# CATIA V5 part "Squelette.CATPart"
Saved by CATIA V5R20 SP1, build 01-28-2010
Part number: Squelette
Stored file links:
  C:\Users\Nicolas\Documents\Ifma\2A\S3\iao\projet\nmine_IAO\Squelette.CATPart

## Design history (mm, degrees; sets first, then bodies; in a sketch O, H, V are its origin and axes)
Parameters
  facteur = 1
  Av = 700 mm
  Ah = 0 mm
  Bv = 0 mm
  Bh = 0 mm
  Cv = -220 mm
  Ch = 0 mm
  Rh = 0 mm
  Rv = -720 mm
  Ev = 220 mm
  Eh = 830 mm
  Dv = 700 mm
  Dh = 1000 mm
  Fv = 850 mm
  Fh = 0 mm
  largeur = 100 mm
Body1 (main body)
  Point1: (0 {= facteur*Bh}, 0 {= facteur*Bh}, 0)
  Point2: type OnPlane, Support yz-plane, H 1000 {= facteur*Dh}, V 700 {= facteur*Dv}, Direction (0, 1, 0)
  Point3: type OnPlane, Support yz-plane, H 0 {= facteur*Fh}, V 850 {= facteur*Fv}, Direction (0, 1, 0)
  Point4: type OnPlane, Support yz-plane, H 0 {= facteur*Ch}, V -220 {= facteur*Cv}, Direction (0, 1, 0)
  Point5: type OnPlane, Support yz-plane, H 0 {= facteur*Rh}, V -720 {= facteur*Rv}, Direction (0, 1, 0)
  Point6: type OnPlane, Support yz-plane, H 0 {= facteur*Ah}, V 700 {= facteur*Av}, Direction (0, 1, 0)
  Point7: type OnPlane, Support yz-plane, H 830 {= facteur*Eh}, V 220 {= facteur*Ev}, Direction (0, 1, 0)
  Line1: type PtDir, RefPoint Point5, Direction yz-plane, Start -20, End 150
  Line2: type PtDir, RefPoint Point4, Direction yz-plane, Start -20, End 150
  Line3: type PtDir, RefPoint Point1, Direction yz-plane, Start -20, End 150
  Line4: type PtDir, RefPoint Point6, Direction yz-plane, Start -20, End 150
  Line5: type PtDir, RefPoint Point3, Direction yz-plane, Start -20, End 150
  Line6: type PtDir, RefPoint Point7, Direction yz-plane, Start -20, End 150
  Line7: type PtDir, RefPoint Point2, Direction yz-plane, Start -20, End 150
  Plane1: type Offset, RefPlane yz-plane, Offset 100 {= largeur}
  Plane2: type Offset, RefPlane Plane1, Offset 100 {= largeur}
  Plane3: type Offset, RefPlane Plane2, Offset 100 {= largeur}
  Plane4: type Offset, RefPlane yz-plane, Offset 50 {= largeur/2}
  Plane5: type Offset, RefPlane Plane1, Offset 50 {= largeur/2}
  Plane6: type Offset, RefPlane Plane2, Offset 50 {= largeur/2}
